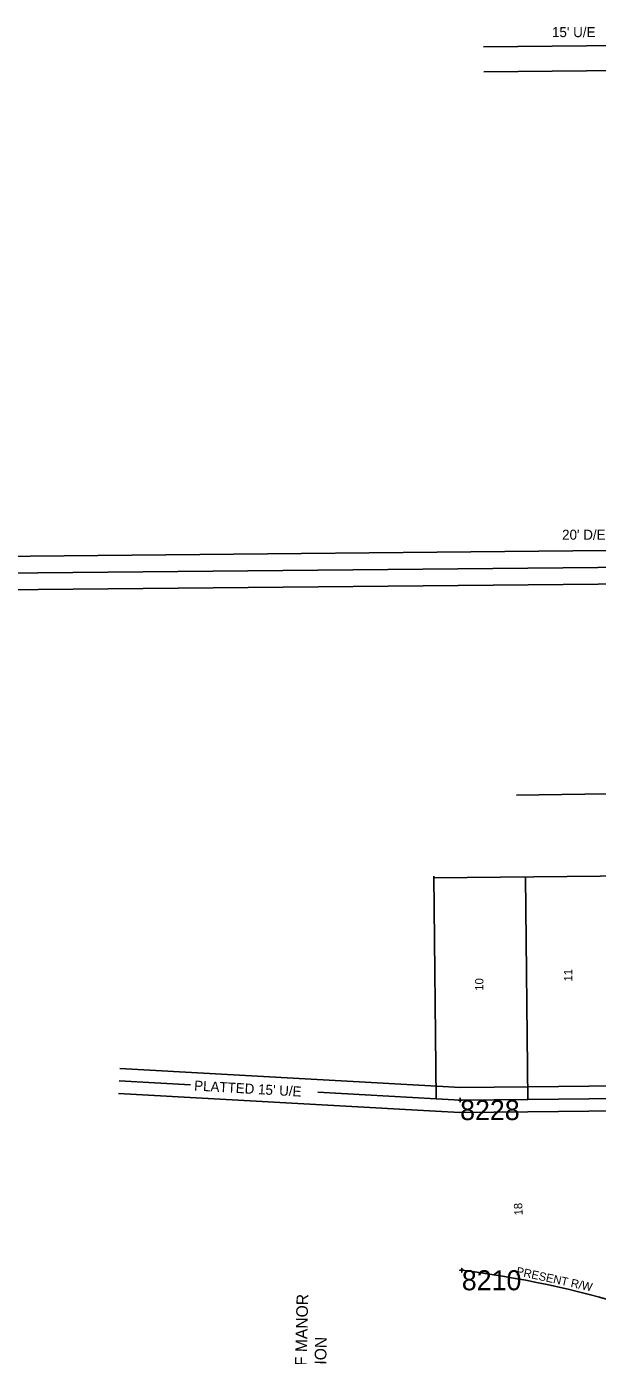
# Model space of a CAD drawing. Extents: x 2145146 to 2158053, y 137507 to 150829.
# Drawn here: x 2149980 to 2150322, y 143925 to 144721 of the extents above; entities that cross this region are included whole.
import ezdxf

# ---------------------------------------------------------------- set-up
doc = ezdxf.new("R2010")
doc.units = 0
for name, color, linetype in [('ALIGN_Cogo Points', 7, 'Continuous'), ('ALIGN_ROW Line', 7, 'Continuous'), ('ALIGN_ROW Text', 7, 'Continuous'), ('PLSS_Block Line', 7, 'Continuous'), ('PLSS_Easement', 7, 'Continuous'), ('PLSS_Lot Line', 7, 'Continuous'), ('PLSS_Text', 7, 'Continuous'), ('PLSS_Text_TURNED OFF', 7, 'Continuous')]:
    doc.layers.add(name, color=color, linetype=linetype)

msp = doc.modelspace()

# ---------------------------------------------------------------- linework, layer by layer
at = {"layer": 'ALIGN_Cogo Points'}
for points in [[(2150239.87, 144077.88), (2150239.87, 144079.08), (2150239.87, 144077.88), (2150238.67, 144077.88), (2150239.87, 144077.88), (2150239.87, 144076.68), (2150239.87, 144077.88), (2150241.07, 144077.88)], [(2150240.87, 143975.84), (2150240.87, 143977.04), (2150240.87, 143975.84), (2150239.67, 143975.84), (2150240.87, 143975.84), (2150240.87, 143974.64), (2150240.87, 143975.84), (2150242.07, 143975.84)]]:
    msp.add_lwpolyline(points, dxfattribs=at)
at = {"layer": 'ALIGN_ROW Line'}
msp.add_arc((2150166.55, 143377.48), 602.96, 73.07114, 82.92018, dxfattribs=at)
at = {"layer": 'PLSS_Block Line'}
for points in [[(2150273.6, 144260.64), (2150491.64, 144263.79), (2150513.97, 144264.01)], [(2150224.14, 144211.13), (2150444.05, 144213.29), (2150507.04, 144213.9)]]:
    msp.add_lwpolyline(points, dxfattribs=at)
at = {"layer": 'PLSS_Easement'}
for points in [[(2150644.84, 144713.12), (2150253.96, 144709.3)], [(2150643.51, 144698.11), (2150254.06, 144694.3)], [(2149839.62, 144402.51), (2150490.22, 144408.84), (2150551.8, 144409.48)], [(2149839.81, 144382.51), (2150490.41, 144388.84), (2150547.39, 144389.44)], [(2150035.91, 144096.82), (2150225.86, 144086.18), (2150240.04, 144085.39), (2150280.35, 144085.78), (2150335.33, 144086.32), (2150390.31, 144086.86), (2150436.64, 144087.31)], [(2150035.07, 144081.85), (2150225.02, 144071.2), (2150239.69, 144070.38), (2150280.5, 144070.78), (2150335.48, 144071.32), (2150390.45, 144071.86), (2150427.05, 144072.21)]]:
    msp.add_lwpolyline(points, dxfattribs=at)
at = {"layer": 'PLSS_Lot Line'}
for points in [[(2149839.72, 144392.51), (2150490.32, 144398.84), (2150547.29, 144399.44)], [(2150225.44, 144078.65), (2150224.14, 144212.04)], [(2150280.43, 144078.24), (2150279.12, 144211.63)], [(2150035.49, 144089.33), (2150078.24, 144086.94)], [(2150154.64, 144082.66), (2150225.44, 144078.69), (2150239.87, 144077.88), (2150280.43, 144078.28), (2150335.4, 144078.82), (2150390.38, 144079.36), (2150431.88, 144079.76)]]:
    msp.add_lwpolyline(points, dxfattribs=at)

# ---------------------------------------------------------------- texts
at = {"layer": 'ALIGN_Cogo Points'}
for s, p in [('8228', (2150239.87, 144065.88)), ('8210', (2150240.87, 143963.84))]:
    msp.add_text(s, height=12, dxfattribs=at).set_placement(p)
at = {"layer": 'ALIGN_ROW Text'}
msp.add_text('PRESENT R/W', height=5, rotation=347.69956, dxfattribs=at).set_placement((2150273.16, 143973.04))
at = {"layer": 'PLSS_Text'}
for s, p in [("15' U/E", (2150294.92, 144715.1)), ("20' D/E & U/E", (2150300.99, 144413.8))]:
    msp.add_text(s, height=6, dxfattribs=at).set_placement(p)
for s, height, rotation, p in [('11', 5, 90, (2150307.13, 144148.98)), ('10', 5, 90, (2150253.8, 144143.46)), ("PLATTED 15' U/E", 6, 356.70403, (2150080.3, 144083.62)), ('18', 5, 92.72733, (2150277.38, 144008.89))]:
    msp.add_text(s, height=height, rotation=rotation, dxfattribs=at).set_placement(p)
at = {"layer": 'PLSS_Text_TURNED OFF'}
for s, p in [('CLOVER LEAF MANOR', (2150146.5, 143859.63)), ('ADDITION', (2150158.92, 143891.12))]:
    msp.add_text(s, height=7, rotation=88.67232, dxfattribs=at).set_placement(p)

doc.saveas('drawing.dxf')
